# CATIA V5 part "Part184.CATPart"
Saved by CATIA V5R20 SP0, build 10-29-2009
Part number: DFA 126700-2 comprimido
Revision: ANY
Definition: UNKNOWN
Nomenclature: DFA 126700-2 comprimido
Source: Unknown
Bounding box of the stored display mesh (mm): x -2.8 to 2.8, y 0 to 5, z -2.8 to 2.8
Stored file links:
  C:\Users\Utente\Desktop\IO LAVORO\3D X SITO CF\CUMSA\3D files FA\FA 126712-21\Part184.CATPart
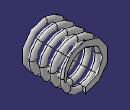
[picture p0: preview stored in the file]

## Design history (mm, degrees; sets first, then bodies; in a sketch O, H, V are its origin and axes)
Body1 "Cortar-Extruir1" (main body)
  Solid1: solid without history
